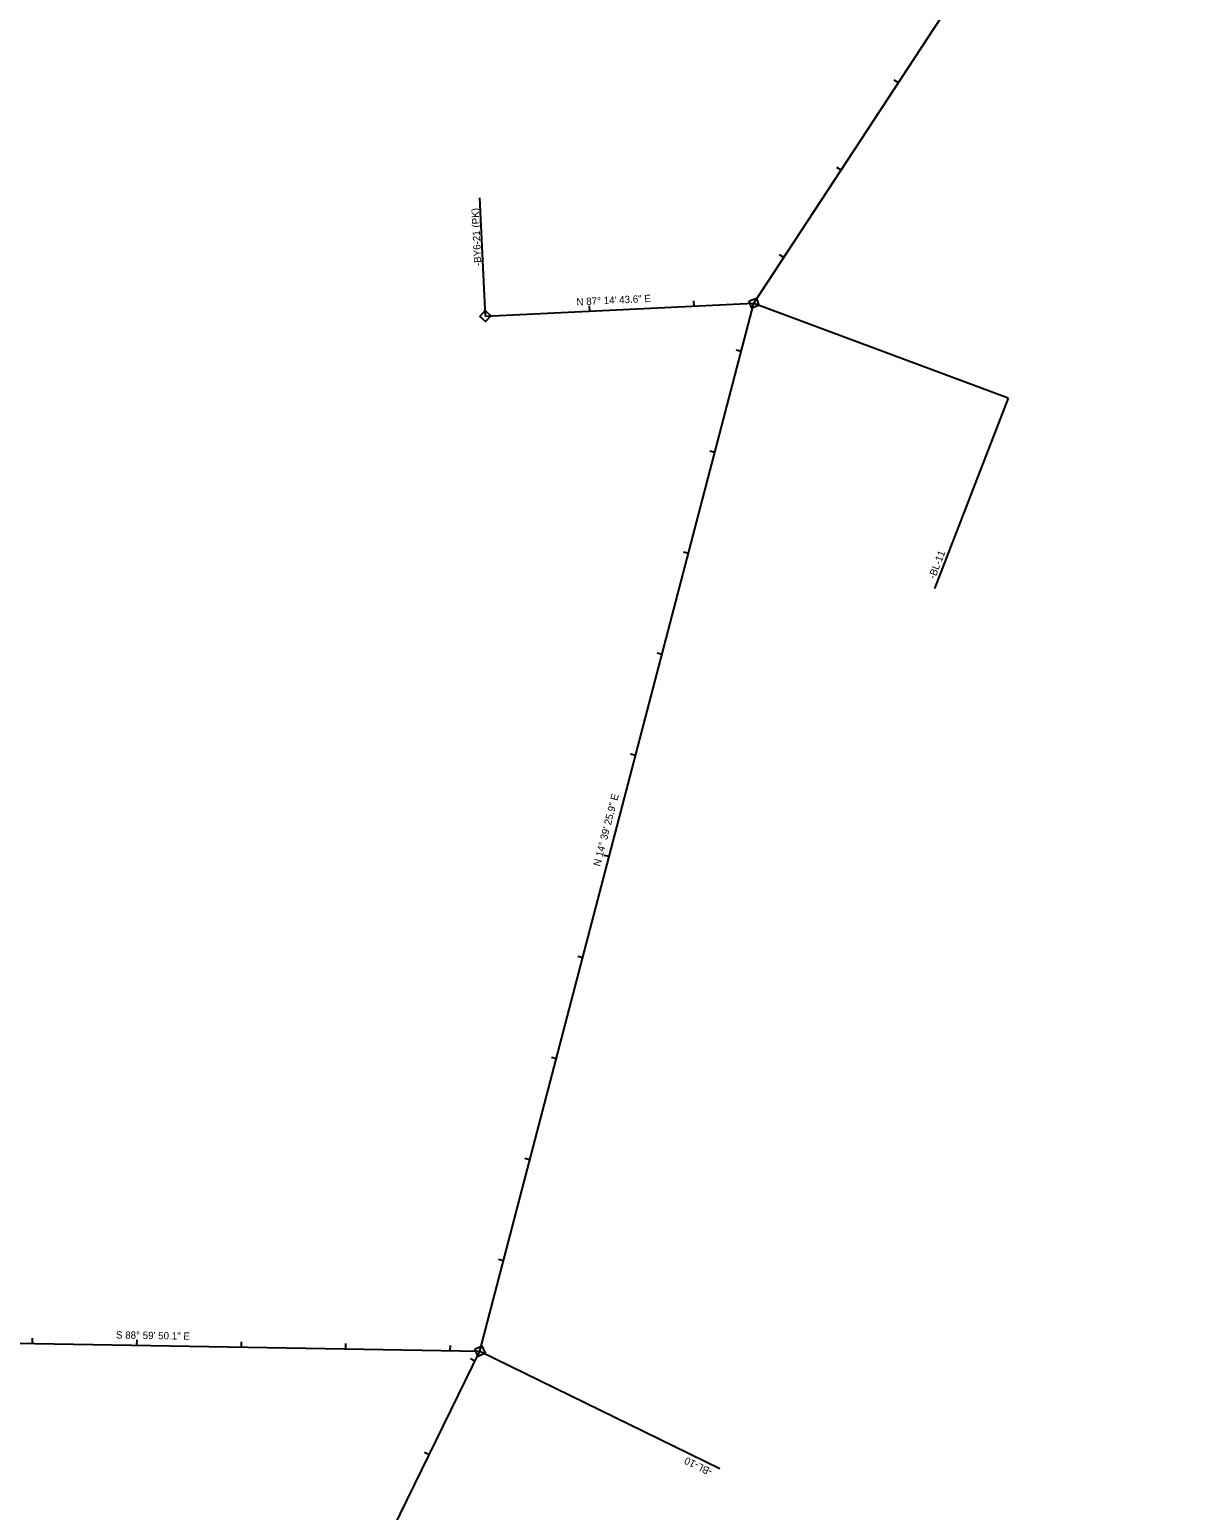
# Model space of a CAD drawing. Extents: x 1975258 to 1978652, y 778250 to 783549.
# Drawn here: x 1977006 to 1978128, y 780713 to 782131 of the extents above; entities that cross this region are included whole.
import ezdxf

# ---------------------------------------------------------------- set-up
doc = ezdxf.new("R2010")
doc.units = 0
for name, color, linetype in [('Prop Drainage Structure Drop Inlet Grate 2 Narrow Slots and Flat Grates 840 29 Label', 7, 'Continuous'), ('Prop Drainage Structure Drop Inlet Grate 2 Narrow Slots and Sag Grates 840 24 CELL', 7, 'Continuous'), ('Prop SS Transition Line', 7, 'Continuous'), ('Sheet Data Field CELL', 7, 'Continuous'), ('Sheet Typical CELL', 7, 'Continuous')]:
    doc.layers.add(name, color=color, linetype=linetype)

msp = doc.modelspace()

# ---------------------------------------------------------------- linework, layer by layer
at = {"layer": 'Prop Drainage Structure Drop Inlet Grate 2 Narrow Slots and Sag Grates 840 24 CELL'}
for p, q in [((1977442.5, 781856.6), (1977437.1, 781970)), ((1977943, 781778.2), (1977699.6, 781868.8)), ((1977943, 781778.2), (1977872.5, 781595.7)), ((1977437.2, 780865.4), (1977667, 780753.1))]:
    msp.add_line(p, q, dxfattribs=at)
at = {"layer": 'Prop SS Transition Line'}
for p, q in [((1977442.5, 781856.6), (1977442.5, 781856.6)), ((1977699.7, 781869), (1977699.7, 781869)), ((1977437.3, 780865.6), (1977437.3, 780865.6))]:
    msp.add_line(p, q, dxfattribs=at)
for points in [[(1977695, 781871.2), (1977702, 781873.8), (1977704.5, 781866.8), (1977697.6, 781864.2)], [(1977437.3, 781856.4), (1977442.3, 781861.9), (1977447.8, 781856.9), (1977442.8, 781851.4)], [(1977432.4, 780867.4), (1977439.1, 780870.5), (1977442.2, 780863.7), (1977435.5, 780860.6)]]:
    msp.add_lwpolyline(points, close=True, dxfattribs=at)
at = {"layer": 'Sheet Data Field CELL'}
for p, q in [((1977838, 782080), (1977833.8, 782082.7)), ((1977783.2, 781996.3), (1977779, 781999.1)), ((1977728.4, 781912.7), (1977724.2, 781915.4)), ((1977642.3, 781866.2), (1977642.1, 781871.2)), ((1977442.5, 781856.6), (1977442.3, 781861.6)), ((1977542.4, 781861.4), (1977542.2, 781866.4)), ((1977687.6, 781822.8), (1977682.8, 781824)), ((1977662.3, 781726), (1977657.5, 781727.3)), ((1977637, 781629.3), (1977632.2, 781630.6)), ((1977611.7, 781532.5), (1977606.9, 781533.8)), ((1977586.4, 781435.8), (1977581.6, 781437.1)), ((1977561.1, 781339.1), (1977556.3, 781340.3)), ((1977535.8, 781242.3), (1977531, 781243.6)), ((1977510.5, 781145.6), (1977505.7, 781146.8)), ((1977485.2, 781048.8), (1977480.4, 781050.1)), ((1977459.9, 780952.1), (1977455.1, 780953.3)), ((1977009, 780873.1), (1977009, 780878)), ((1977108.9, 780871.3), (1977109, 780876.3)), ((1977208.9, 780869.6), (1977209, 780874.5)), ((1977308.9, 780867.8), (1977309, 780872.8)), ((1977408.9, 780866.1), (1977409, 780871)), ((1977432.6, 780856.1), (1977428.2, 780858.2)), ((1977388.7, 780766.2), (1977384.3, 780768.4))]:
    msp.add_line(p, q, dxfattribs=at)
at = {"layer": 'Sheet Typical CELL'}
for p, q in [((1977699.7, 781869), (1978128.1, 782522.8)), ((1977437.3, 780865.6), (1977699.7, 781869)), ((1977442.5, 781856.6), (1977699.7, 781869)), ((1976822.2, 780876.3), (1977437.3, 780865.6)), ((1977137.6, 780252.1), (1977437.3, 780865.6))]:
    msp.add_line(p, q, dxfattribs=at)

# ---------------------------------------------------------------- texts
at = {"layer": 'Prop Drainage Structure Drop Inlet Grate 2 Narrow Slots and Flat Grates 840 29 Label'}
for s, rotation, p in [('N 87%%d 14\' 43.6" E', 2.7546, (1977529.9, 781866.8)), ('N 14%%d 39\' 25.9" E', 75.3428, (1977552.4, 781329.3)), ('S 88%%d 59\' 50.1" E', 358.9973, (1977088.8, 780877.7))]:
    msp.add_text(s, height=7, rotation=rotation, dxfattribs=at).set_placement(p)
at = {"layer": 'Prop Drainage Structure Drop Inlet Grate 2 Narrow Slots and Sag Grates 840 24 CELL'}
for s, rotation, p in [('-BY6-21 (PK)', 92.7546, (1977438.8, 781904.7)), ('-BL-11', 68.8203, (1977872.9, 781604.4)), ('-BL-10', 153.963, (1977660.5, 780752.2))]:
    msp.add_text(s, height=7, rotation=rotation, dxfattribs=at).set_placement(p)

doc.saveas('drawing.dxf')
